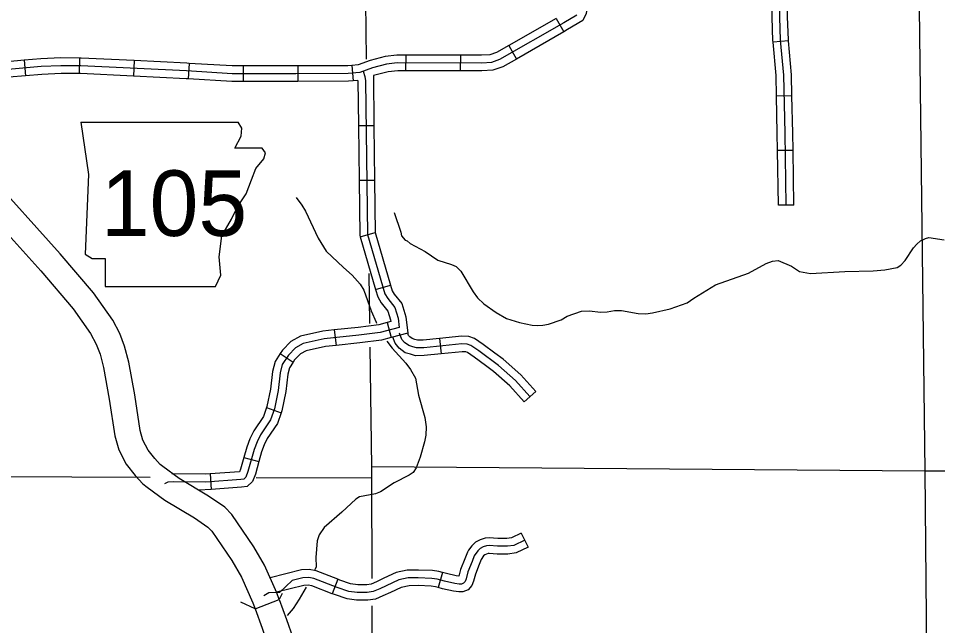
# Model space of a CAD drawing. Extents: x 1373862 to 1376999, y 1168398 to 1170455.
# Drawn here: x 1374862.3 to 1375039.9, y 1169076.3 to 1169193.7 of the extents above; entities that cross this region are included whole.
import ezdxf

# ---------------------------------------------------------------- set-up
doc = ezdxf.new("R2010")
doc.units = 0
for name, color, linetype in [('Level 10', 7, 'Continuous'), ('Level 21', 7, 'Continuous'), ('Level 32', 7, 'Continuous'), ('Level 35', 7, 'Continuous'), ('Level 37', 7, 'Continuous'), ('Level 4', 7, 'Continuous'), ('Level 45', 7, 'Continuous'), ('Level 5', 7, 'Continuous')]:
    doc.layers.add(name, color=color, linetype=linetype)

msp = doc.modelspace()

# ---------------------------------------------------------------- linework, layer by layer
at = {"layer": 'Level 10'}
msp.add_line((1374907.99, 1169079.58), (1374912.68, 1169081.32), dxfattribs=at)
for points in [[(1374912.68, 1169081.32), (1374912.2, 1169082.61), (1374909.82, 1169087.97), (1374907.77, 1169091.52), (1374903.53, 1169097.75), (1374902.13, 1169099.19), (1374899, 1169101.33), (1374893.36, 1169104.73), (1374890.18, 1169107.06), (1374889.67, 1169107.45), (1374888.61, 1169108.57), (1374887.35, 1169110.18), (1374886.34, 1169112.14), (1374885.79, 1169114.03), (1374884.78, 1169120.9), (1374883.61, 1169127.25), (1374882.8, 1169130.33), (1374881.84, 1169132.76), (1374880.5, 1169135.36), (1374876.78, 1169140.62), (1374870.34, 1169148.18), (1374856.17, 1169163.87), (1374843.25, 1169175.79)], [(1374839.88, 1169172.1), (1374852.61, 1169160.35), (1374866.58, 1169144.89), (1374872.83, 1169137.54), (1374876.22, 1169132.76), (1374877.28, 1169130.69), (1374878.04, 1169128.78), (1374878.72, 1169126.16), (1374879.84, 1169120.09), (1374880.89, 1169112.96), (1374881.68, 1169110.27), (1374883.12, 1169107.48), (1374884.81, 1169105.3), (1374886.31, 1169103.73), (1374887.18, 1169103.06), (1374890.59, 1169100.56), (1374896.3, 1169097.12), (1374898.89, 1169095.35), (1374899.64, 1169094.58), (1374903.53, 1169088.86), (1374905.36, 1169085.7), (1374907.56, 1169080.72), (1374907.99, 1169079.58)], [(1374912.68, 1169081.32), (1374914.09, 1169077.49), (1374915.29, 1169074.03), (1374915.65, 1169071.86), (1374915.63, 1169070.48)], [(1374907.99, 1169079.58), (1374909.39, 1169075.8), (1374910.43, 1169072.79), (1374910.65, 1169071.49), (1374910.63, 1169070.56)]]:
    msp.add_lwpolyline(points, dxfattribs=at)
at = {"layer": 'Level 21'}
for p, q in [((1374874.32, 1169173.62), (1374875.84, 1169163.47)), ((1374905.45, 1169172.44), (1374904.75, 1169173.61)), ((1374905.28, 1169170.92), (1374905.45, 1169172.44)), ((1374904.1, 1169168.55), (1374905.28, 1169170.92)), ((1374909.34, 1169168.55), (1374904.1, 1169168.55)), ((1374910.02, 1169167.7), (1374909.34, 1169168.55)), ((1374908.16, 1169164.66), (1374909.68, 1169166.52)), ((1374909.68, 1169166.52), (1374910.02, 1169167.7)), ((1374907.31, 1169162.46), (1374908.16, 1169164.66)), ((1374875.84, 1169163.47), (1374875.17, 1169148.08)), ((1374906.29, 1169159.75), (1374907.31, 1169162.46)), ((1374904.6, 1169157.21), (1374906.29, 1169159.75)), ((1374903.42, 1169154.85), (1374904.6, 1169157.21)), ((1374901.56, 1169151.63), (1374903.42, 1169154.85)), ((1374901.05, 1169147.57), (1374901.56, 1169151.63)), ((1374875.17, 1169148.08), (1374876.52, 1169147.23)), ((1374876.52, 1169147.23), (1374879.06, 1169147.23)), ((1374879.06, 1169147.23), (1374879.06, 1169141.82)), ((1374901.39, 1169144.02), (1374901.05, 1169147.57)), ((1374900.37, 1169141.82), (1374901.39, 1169144.02)), ((1374879.06, 1169141.82), (1374900.37, 1169141.82))]:
    msp.add_line(p, q, dxfattribs=at)
msp.add_lwpolyline([(1374874.32, 1169173.62), (1374904.75, 1169173.61)], dxfattribs=at)
at = {"layer": 'Level 32'}
for p, q in [((1374966.16, 1169193.66), (1374967.65, 1169191.06)), ((1374957, 1169188.41), (1374958.49, 1169185.8)), ((1375011.06, 1169189.35), (1375008.07, 1169189.07)), ((1374874.06, 1169185.99), (1374874.04, 1169182.99)), ((1374937.1, 1169186.54), (1374937.09, 1169183.54)), ((1374947.66, 1169186.52), (1374947.65, 1169183.52)), ((1374863.38, 1169185.56), (1374863.63, 1169182.57)), ((1374884.67, 1169185.49), (1374884.53, 1169182.49)), ((1374895.24, 1169184.97), (1374895.06, 1169181.98)), ((1374905.69, 1169184.47), (1374905.69, 1169181.47)), ((1374916.25, 1169184.47), (1374916.26, 1169181.47)), ((1374926.69, 1169184.57), (1374926.93, 1169181.58)), ((1375011.73, 1169178.71), (1375008.73, 1169178.65)), ((1374927.97, 1169172.93), (1374930.97, 1169172.96)), ((1375011.93, 1169168.14), (1375008.93, 1169168.1)), ((1374928.1, 1169162.37), (1374931.1, 1169162.4)), ((1375012.1, 1169157.58), (1375009.1, 1169157.54)), ((1374928.31, 1169151.41), (1374931.19, 1169152.25)), ((1374931.27, 1169141.27), (1374934.15, 1169142.12)), ((1374933.52, 1169134.86), (1374934.32, 1169131.97)), ((1374923.31, 1169133.44), (1374923.64, 1169130.46)), ((1374912.87, 1169128.9), (1374915.37, 1169127.25)), ((1374910.23, 1169118.44), (1374913.06, 1169117.44)), ((1374905.84, 1169108.82), (1374908.73, 1169108.01)), ((1374899.32, 1169105.62), (1374899.53, 1169102.62))]:
    msp.add_line(p, q, dxfattribs=at)
for points in [[(1375010.6, 1169157.56), (1375010.38, 1169171.48), (1375010.16, 1169182.67), (1375009.54, 1169189.43), (1375009.37, 1169193.9), (1375009.15, 1169211.48)], [(1374972.37, 1169200.94), (1374972.2, 1169196.42), (1374971.94, 1169194.62), (1374971.3, 1169193.27), (1374968.39, 1169191.48), (1374967.65, 1169191.06)], [(1375008.07, 1169189.07), (1375008.04, 1169189.33), (1375007.87, 1169193.87), (1375007.79, 1169199.75)], [(1375011.06, 1169189.35), (1375011.04, 1169189.52), (1375010.87, 1169193.94), (1375010.79, 1169199.78)], [(1374970.13, 1169194.31), (1374967.62, 1169192.77), (1374955.25, 1169185.68), (1374953.67, 1169185.15), (1374951.78, 1169185.02), (1374935.48, 1169185.04), (1374933.41, 1169184.82), (1374930.69, 1169184.11), (1374928.22, 1169183.19), (1374925.98, 1169183.01), (1374915.87, 1169182.97), (1374903.55, 1169182.97), (1374894.74, 1169183.5), (1374874.34, 1169184.49), (1374870.5, 1169184.51), (1374866.68, 1169184.34), (1374860.29, 1169183.8), (1374854.53, 1169183.03), (1374853.62, 1169182.77), (1374852.36, 1169182.19), (1374849.21, 1169180.48), (1374846.22, 1169178.59), (1374840.91, 1169174.54)], [(1374966.16, 1169193.66), (1374957, 1169188.41)], [(1374967.65, 1169191.06), (1374958.49, 1169185.8)], [(1374957, 1169188.41), (1374954.64, 1169187.05), (1374953.38, 1169186.63), (1374951.72, 1169186.52), (1374947.66, 1169186.52)], [(1375008.73, 1169178.65), (1375008.66, 1169182.59), (1375008.07, 1169189.07)], [(1375011.73, 1169178.71), (1375011.65, 1169182.75), (1375011.06, 1169189.35)], [(1374874.06, 1169185.99), (1374870.47, 1169186.01), (1374866.58, 1169185.83), (1374863.38, 1169185.56)], [(1374884.67, 1169185.49), (1374874.38, 1169185.99), (1374874.06, 1169185.99)], [(1374937.1, 1169186.54), (1374935.41, 1169186.54), (1374933.15, 1169186.3), (1374930.23, 1169185.55), (1374927.89, 1169184.67), (1374926.69, 1169184.57)], [(1374947.66, 1169186.52), (1374937.1, 1169186.54)], [(1374863.38, 1169185.56), (1374860.13, 1169185.29), (1374854.22, 1169184.5), (1374853.1, 1169184.18), (1374852.47, 1169183.89)], [(1374895.24, 1169184.97), (1374894.82, 1169184.99), (1374884.67, 1169185.49)], [(1374905.69, 1169184.47), (1374903.59, 1169184.47), (1374895.24, 1169184.97)], [(1374916.25, 1169184.47), (1374915.87, 1169184.47), (1374905.69, 1169184.47)], [(1374926.69, 1169184.57), (1374925.91, 1169184.51), (1374916.25, 1169184.47)], [(1374958.49, 1169185.8), (1374955.87, 1169184.3), (1374953.96, 1169183.67), (1374951.83, 1169183.52), (1374947.65, 1169183.52)], [(1374863.63, 1169182.57), (1374860.46, 1169182.31), (1374854.83, 1169181.55), (1374854.14, 1169181.36), (1374853.72, 1169181.17)], [(1374874.04, 1169182.99), (1374870.53, 1169183.01), (1374866.78, 1169182.84), (1374863.63, 1169182.57)], [(1374884.53, 1169182.49), (1374874.29, 1169182.99), (1374874.04, 1169182.99)], [(1374895.06, 1169181.98), (1374894.66, 1169182), (1374884.53, 1169182.49)], [(1374928.9, 1169183.44), (1374929.23, 1169182.4), (1374929.36, 1169181.56), (1374929.72, 1169151.92), (1374933.09, 1169140.42), (1374933.62, 1169139.53), (1374935.02, 1169137.81), (1374935.64, 1169135.7), (1374935.85, 1169133.94), (1374932.16, 1169132.93), (1374928.06, 1169132.46), (1374921.36, 1169131.71), (1374917.31, 1169130.82), (1374915.83, 1169130.01), (1374914.46, 1169128.59), (1374913.24, 1169126.74), (1374912.82, 1169125.16), (1374912.46, 1169121.77), (1374911.75, 1169118.22), (1374910.98, 1169116.05), (1374909.04, 1169113.19), (1374908.39, 1169111.82), (1374907.82, 1169110.33), (1374906.63, 1169106.08), (1374906.21, 1169105.01), (1374905.8, 1169104.59), (1374905.26, 1169104.53), (1374898.48, 1169104.05), (1374892.32, 1169104.11), (1374891.13, 1169104.02), (1374890.53, 1169103.7)], [(1374937.09, 1169183.54), (1374935.56, 1169183.54), (1374933.68, 1169183.34), (1374930.85, 1169182.61)], [(1374930.85, 1169182.61), (1374930.97, 1169172.96)], [(1374947.65, 1169183.52), (1374937.09, 1169183.54)], [(1374905.69, 1169181.47), (1374903.5, 1169181.47), (1374895.06, 1169181.98)], [(1374916.26, 1169181.47), (1374915.88, 1169181.47), (1374905.69, 1169181.47)], [(1374926.93, 1169181.58), (1374926.04, 1169181.51), (1374916.26, 1169181.47)], [(1374927.86, 1169181.66), (1374926.93, 1169181.58)], [(1374927.86, 1169181.66), (1374927.97, 1169172.93)], [(1375008.93, 1169168.1), (1375008.88, 1169171.45), (1375008.73, 1169178.65)], [(1375011.93, 1169168.14), (1375011.88, 1169171.5), (1375011.73, 1169178.71)], [(1374927.97, 1169172.93), (1374928.1, 1169162.37)], [(1374930.97, 1169172.96), (1374931.1, 1169162.4)], [(1375009.1, 1169157.54), (1375008.93, 1169168.1)], [(1375012.1, 1169157.58), (1375011.93, 1169168.14)], [(1374928.1, 1169162.37), (1374928.23, 1169151.69), (1374928.31, 1169151.41)], [(1374931.1, 1169162.4), (1374931.22, 1169152.14), (1374931.19, 1169152.25)], [(1374931.19, 1169152.25), (1374934.15, 1169142.12)], [(1374928.31, 1169151.41), (1374931.27, 1169141.27)], [(1374934.15, 1169142.12), (1374934.47, 1169141.03), (1374934.85, 1169140.39), (1374936.37, 1169138.53), (1374937.12, 1169136), (1374937.49, 1169132.84), (1374934.32, 1169131.97)], [(1374931.27, 1169141.27), (1374931.7, 1169139.82), (1374932.39, 1169138.67), (1374933.67, 1169137.1), (1374934.17, 1169135.4), (1374934.21, 1169135.05), (1374933.52, 1169134.86)], [(1374933.52, 1169134.86), (1374931.88, 1169134.41), (1374927.89, 1169133.95), (1374923.31, 1169133.44)], [(1374923.31, 1169133.44), (1374921.12, 1169133.19), (1374916.79, 1169132.24), (1374914.91, 1169131.22), (1374913.28, 1169129.53), (1374912.87, 1169128.9)], [(1374934.32, 1169131.97), (1374932.45, 1169131.46), (1374928.23, 1169130.97), (1374923.64, 1169130.46)], [(1374923.64, 1169130.46), (1374921.61, 1169130.23), (1374917.84, 1169129.4), (1374916.75, 1169128.81), (1374915.63, 1169127.65), (1374915.37, 1169127.25)], [(1374912.87, 1169128.9), (1374911.85, 1169127.36), (1374911.34, 1169125.43), (1374910.98, 1169121.99), (1374910.3, 1169118.63), (1374910.23, 1169118.44)], [(1374915.37, 1169127.25), (1374914.62, 1169126.12), (1374914.3, 1169124.89), (1374913.95, 1169121.54), (1374913.2, 1169117.82), (1374913.06, 1169117.44)], [(1374910.23, 1169118.44), (1374909.63, 1169116.73), (1374907.74, 1169113.94), (1374907.01, 1169112.41), (1374906.39, 1169110.8), (1374905.84, 1169108.82)], [(1374913.06, 1169117.44), (1374912.32, 1169115.37), (1374910.35, 1169112.45), (1374909.77, 1169111.23), (1374909.25, 1169109.87), (1374908.73, 1169108.01)], [(1374905.84, 1169108.82), (1374905.21, 1169106.55), (1374905, 1169106.01), (1374899.32, 1169105.62)], [(1374908.73, 1169108.01), (1374908.06, 1169105.6), (1374907.5, 1169104.17), (1374906.49, 1169103.16), (1374905.4, 1169103.04), (1374899.53, 1169102.62)], [(1374899.32, 1169105.62), (1374898.43, 1169105.55), (1374891.89, 1169105.62)], [(1374899.53, 1169102.62), (1374897.13, 1169102.45)]]:
    msp.add_lwpolyline(points, dxfattribs=at)
at = {"layer": 'Level 35'}
for points in [[(1374915.96, 1169159.01), (1374917.06, 1169157.59), (1374917.76, 1169156.39), (1374920.16, 1169151.16), (1374921.76, 1169148.68), (1374925.06, 1169145.5), (1374926.77, 1169144.03), (1374928.31, 1169142.29), (1374928.99, 1169141.13), (1374930.43, 1169137.13), (1374931.38, 1169134.96), (1374931.47, 1169134.78)], [(1374934.86, 1169156.16), (1374936.13, 1169152.33), (1374936.29, 1169151.65), (1374936.98, 1169150.82), (1374937.38, 1169150.66), (1374937.97, 1169150.15), (1374940.87, 1169148.61), (1374943.29, 1169146.92), (1374945.92, 1169146.12), (1374946.85, 1169145.72), (1374947.76, 1169144.81), (1374950.14, 1169140.82), (1374950.98, 1169139.67), (1374952.18, 1169138.48), (1374954.6, 1169136.81), (1374956.58, 1169135.66), (1374959.07, 1169134.86), (1374961.54, 1169134.4), (1374962.52, 1169134.33), (1374963.61, 1169134.37), (1374964.71, 1169134.56), (1374967.12, 1169135.38), (1374968.29, 1169136.12), (1374971.07, 1169137.05), (1374972.55, 1169137.13), (1374974.77, 1169136.88), (1374976.05, 1169136.94), (1374977.44, 1169137.2), (1374978.8, 1169137.18), (1374981.99, 1169136.61), (1374983.49, 1169136.58), (1374984.79, 1169136.74), (1374988.19, 1169137.51), (1374991.48, 1169138.66), (1374992.76, 1169139.6), (1374996.94, 1169142.17), (1375003.3, 1169144.39), (1375006.71, 1169146.27), (1375007.94, 1169146.73), (1375009.04, 1169146.89), (1375011.66, 1169145.74), (1375013.17, 1169144.75), (1375015.32, 1169144.36), (1375021.95, 1169144.74), (1375027.38, 1169144.86), (1375029.64, 1169145.06), (1375032.05, 1169145.51), (1375032.76, 1169145.95), (1375033.57, 1169146.88), (1375035.21, 1169149.29), (1375035.84, 1169150), (1375036.55, 1169150.67), (1375037.5, 1169151.15), (1375038.18, 1169151.32), (1375041.15, 1169150.86)], [(1374933.43, 1169131.29), (1374934.48, 1169129.91), (1374937.12, 1169127.01), (1374938, 1169125.8), (1374939, 1169124.11), (1374939.59, 1169120.83), (1374940.78, 1169116.52), (1374941.04, 1169114.72), (1374940.97, 1169113.1), (1374940.75, 1169111.83), (1374939.87, 1169108.89), (1374939.13, 1169106.83), (1374938.52, 1169105.9), (1374937.77, 1169105.39), (1374934.87, 1169103.9), (1374932.22, 1169102.16), (1374931.29, 1169101.78), (1374928.18, 1169101.2), (1374927.44, 1169100.74), (1374924.78, 1169098.22), (1374921.33, 1169095.28), (1374920.37, 1169093.86), (1374919.97, 1169092.69), (1374919.76, 1169089.5), (1374919.77, 1169087.68), (1374919.52, 1169087.11)], [(1374917.85, 1169083.75), (1374916.54, 1169081.44), (1374915.33, 1169079.59), (1374914.17, 1169078.23)]]:
    msp.add_lwpolyline(points, dxfattribs=at)
at = {"layer": 'Level 37'}
for points in [[(1374913.23, 1169082.52), (1374912.68, 1169081.32)], [(1374907.99, 1169079.58), (1374905.26, 1169080.84)]]:
    msp.add_lwpolyline(points, dxfattribs=at)
at = {"layer": 'Level 4'}
for points in [[(1374929.2, 1169207.98), (1374929.48, 1169185.76)], [(1374930, 1169144.38), (1374930.12, 1169134.68)], [(1374930.18, 1169130.13), (1374930.47, 1169106.96), (1374930.48, 1169104.81), (1374930.55, 1169085.4)], [(1374930.57, 1169080.13), (1374930.88, 1169000.77), (1374930.9, 1168998.52), (1374930.92, 1168993.33)]]:
    msp.add_lwpolyline(points, dxfattribs=at)
at = {"layer": 'Level 45'}
for p, q in [((1374943.64, 1169131.81), (1374943.94, 1169128.83)), ((1374962.22, 1169121.56), (1374959.99, 1169119.55)), ((1374959.43, 1169094.17), (1374960.75, 1169091.47)), ((1374944.2, 1169086.56), (1374943.38, 1169083.68)), ((1374923.97, 1169085.26), (1374922.89, 1169082.46))]:
    msp.add_line(p, q, dxfattribs=at)
for points in [[(1374961.1, 1169120.56), (1374958.28, 1169123.68), (1374955.01, 1169126.6), (1374951.2, 1169129.43), (1374949.71, 1169130.44), (1374949, 1169130.68), (1374947.96, 1169130.74), (1374940.58, 1169130), (1374939.19, 1169129.96), (1374938.45, 1169130.19), (1374937.69, 1169130.41), (1374936.86, 1169131.01), (1374936.35, 1169131.63), (1374935.89, 1169132.84)], [(1374943.64, 1169131.81), (1374940.48, 1169131.49), (1374939.4, 1169131.47), (1374938.88, 1169131.63), (1374938.36, 1169131.78), (1374937.89, 1169132.11), (1374937.67, 1169132.39), (1374937.49, 1169132.84)], [(1374943.94, 1169128.83), (1374940.67, 1169128.5), (1374938.98, 1169128.46), (1374938.02, 1169128.75), (1374937.02, 1169129.04), (1374935.82, 1169129.91), (1374935.04, 1169130.87), (1374934.59, 1169132.04)], [(1374954.33, 1169128.98), (1374952.07, 1169130.65), (1374950.38, 1169131.8), (1374949.28, 1169132.17), (1374947.92, 1169132.24), (1374943.64, 1169131.81)], [(1374952.54, 1169126.57), (1374950.33, 1169128.21), (1374949.04, 1169129.09), (1374948.71, 1169129.19), (1374947.99, 1169129.24), (1374943.94, 1169128.83)], [(1374962.22, 1169121.56), (1374959.33, 1169124.75), (1374955.96, 1169127.77), (1374954.33, 1169128.98)], [(1374959.99, 1169119.55), (1374957.22, 1169122.62), (1374954.06, 1169125.44), (1374952.54, 1169126.57)], [(1374959.43, 1169094.17), (1374957.55, 1169093.25), (1374956.65, 1169093.14), (1374954.93, 1169093.14), (1374953.23, 1169093.28), (1374952.44, 1169093.22), (1374951.49, 1169092.91), (1374950.59, 1169092.42), (1374949.88, 1169091.73), (1374949.26, 1169090.87)], [(1374960.09, 1169092.82), (1374957.99, 1169091.8), (1374956.75, 1169091.64), (1374954.86, 1169091.64), (1374953.23, 1169091.78), (1374952.74, 1169091.74), (1374952.08, 1169091.52), (1374951.49, 1169091.2), (1374951.02, 1169090.74), (1374950.35, 1169089.81), (1374949.92, 1169088.67), (1374949.13, 1169086.7), (1374948.78, 1169085.34), (1374948.6, 1169084.85), (1374948.29, 1169084.5), (1374947.86, 1169084.34), (1374947.45, 1169084.34), (1374946.6, 1169084.43), (1374944.6, 1169084.89), (1374943.17, 1169085.3), (1374942.17, 1169085.43), (1374939.53, 1169085.54), (1374937.58, 1169085.51), (1374935.75, 1169085.13), (1374932.08, 1169083.4), (1374930.84, 1169082.89), (1374929.68, 1169082.7), (1374927.72, 1169082.7), (1374926.1, 1169082.92), (1374923.84, 1169083.7), (1374919.37, 1169085.43), (1374918.37, 1169085.62), (1374917.22, 1169085.57), (1374915.16, 1169085.05), (1374912.69, 1169082.72), (1374910.64, 1169082.62), (1374909.69, 1169082.09)], [(1374949.26, 1169090.87), (1374949.01, 1169090.53), (1374948.52, 1169089.21), (1374947.71, 1169087.16), (1374947.37, 1169085.86), (1374946.85, 1169085.92), (1374944.97, 1169086.35), (1374944.2, 1169086.56)], [(1374960.75, 1169091.47), (1374958.43, 1169090.34), (1374956.85, 1169090.14), (1374954.8, 1169090.14), (1374953.23, 1169090.27), (1374953.04, 1169090.26), (1374952.68, 1169090.14), (1374952.39, 1169089.98), (1374952.16, 1169089.76), (1374951.69, 1169089.11)], [(1374951.69, 1169089.11), (1374951.68, 1169089.09), (1374951.31, 1169088.12), (1374950.56, 1169086.23), (1374950.21, 1169084.88), (1374949.9, 1169084.06), (1374949.16, 1169083.23), (1374948.13, 1169082.84), (1374947.37, 1169082.84), (1374946.35, 1169082.95), (1374944.22, 1169083.44), (1374943.38, 1169083.68)], [(1374923.97, 1169085.26), (1374919.79, 1169086.87), (1374918.48, 1169087.13), (1374917, 1169087.06), (1374910.9, 1169085.54)], [(1374944.2, 1169086.56), (1374943.47, 1169086.77), (1374942.3, 1169086.93), (1374939.55, 1169087.04), (1374937.41, 1169087), (1374935.27, 1169086.56), (1374932.9, 1169085.45)], [(1374932.9, 1169085.45), (1374931.48, 1169084.78), (1374930.43, 1169084.34), (1374929.56, 1169084.2), (1374927.82, 1169084.2), (1374926.45, 1169084.39), (1374924.35, 1169085.11), (1374923.97, 1169085.26)], [(1374922.89, 1169082.46), (1374918.95, 1169083.98), (1374918.26, 1169084.11), (1374917.44, 1169084.08), (1374912.13, 1169082.76)], [(1374943.38, 1169083.68), (1374942.86, 1169083.82), (1374942.04, 1169083.94), (1374939.51, 1169084.04), (1374937.74, 1169084.01), (1374936.22, 1169083.7), (1374934.18, 1169082.73)], [(1374934.18, 1169082.73), (1374932.69, 1169082.03), (1374931.26, 1169081.44), (1374929.81, 1169081.2), (1374927.62, 1169081.2), (1374925.76, 1169081.45), (1374923.33, 1169082.29), (1374922.89, 1169082.46)]]:
    msp.add_lwpolyline(points, dxfattribs=at)
at = {"layer": 'Level 5'}
for points in [[(1375036.08, 1169211.47), (1375037.4, 1169106.13)], [(1375037.4, 1169106.13), (1374930.47, 1169106.96)], [(1375048.68, 1169106.17), (1375037.4, 1169106.13)], [(1375037.4, 1169106.13), (1375038.34, 1169000.46)], [(1374887.73, 1169104.96), (1374842.32, 1169105.12)], [(1374930.48, 1169104.81), (1374908.21, 1169104.89)]]:
    msp.add_lwpolyline(points, dxfattribs=at)

# ---------------------------------------------------------------- texts
at = {"layer": 'Level 21'}
msp.add_text('105', height=12.672, dxfattribs=at).set_placement((1374878.2, 1169151.61))

doc.saveas('drawing.dxf')
